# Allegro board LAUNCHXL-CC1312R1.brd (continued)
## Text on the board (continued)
XSECTION_CHART: L1: TOP CONDUCTOR - COPPER + PLATING 0.035 MM | *  DIELECTRIC - FR-4 0.175 MM (TOP PRIORITY) | L2: L2 PLANE - COPPER 0.035 MM | *  DIELECTRIC - FR-4 1.11 MM | L3: L3 PLANE - COPPER 0.035 MM | *  DIELECTRIC - FR-4 0.175 MM | L4: BOTTOM CONDUCTOR - COPPER + PLATING 0.035 MM | DESIGN CROSS SECTION CHART | ___________________________ | TOTAL THICKNESS 1.6 MM
PAGE_OUTLINE: 2018-10-10 | TA,SJ | PM | FABRICATION DRAWING | LAUNCHXL-CC1312R1 | CC1312R LaunchPad | WCS042 D | NONE | 1 OF 1
User.27: FIGURE | FINISHED_SIZE | 0.2 | 0.201 | 1.05 | 1.1 | 3.2 | 0.899 | 1.0 | 1.3x0.6 | DRILL CHART: TOP to BOTTOM | ALL UNITS ARE IN MILLIMETERS | ROTATION | - | 90.000 | PLATED | NON-PLATED | QTY | 1369 | 25 | 75 | 1 | 4 | 6 | 3 | 2 | 1487 | TOTAL HOLES:
